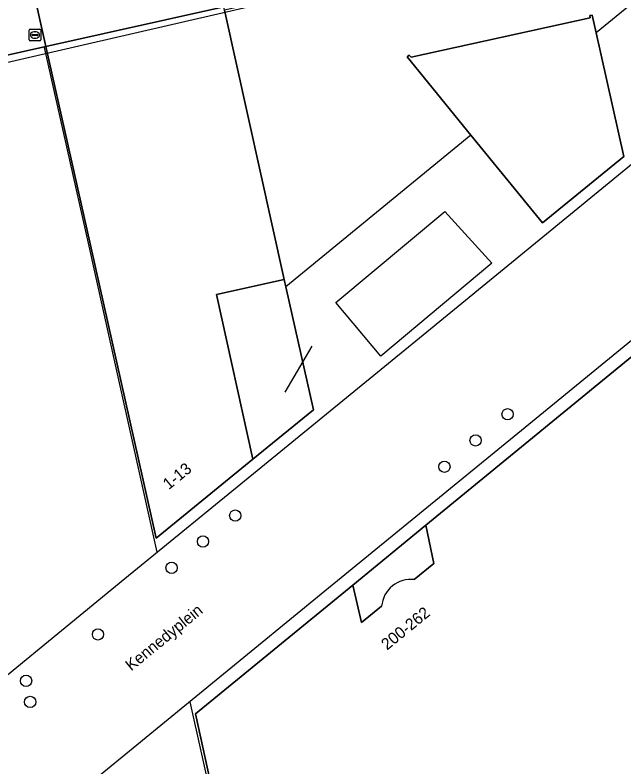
# Model space of a CAD drawing. Extents: x 160806 to 161707, y 383696 to 384148.
# Drawn here: x 161436.7 to 161489.3, y 383865.4 to 383930.4 of the extents above; entities that cross this region are included whole.
import ezdxf

# ---------------------------------------------------------------- set-up
doc = ezdxf.new("R2010")
doc.units = 0
for name, color, linetype in [('IMGEO_Boom', 7, 'Continuous'), ('IMGEO_Kolk', 7, 'Continuous'), ('IMGEO_Lage_trafo', 7, 'Continuous'), ('IMGEO_Lijnafwatering', 7, 'Continuous'), ('IMGEO_Muur', 7, 'Continuous'), ('IMGEO_Openbare_ruimte_label', 7, 'Continuous'), ('IMGEO_Pand', 7, 'Continuous'), ('IMGEO_Pand_nummerreeks', 7, 'Continuous'), ('IMGEO_Pand_overbouw', 7, 'Continuous'), ('IMGEO_Pand_vergunning_verleend', 7, 'Continuous'), ('IMGEO_Rijbaan_lokaal_open', 7, 'Continuous'), ('IMGEO_Voetgangersgebied_open', 7, 'Continuous'), ('IMGEO_Voetpad_open', 7, 'Continuous')]:
    doc.layers.add(name, color=color, linetype=linetype)

msp = doc.modelspace()

# ---------------------------------------------------------------- linework, layer by layer
at = {"layer": 'IMGEO_Boom'}
for centre in [(161479.28, 383895.862), (161476.511, 383893.603), (161473.815, 383891.327), (161455.746, 383887.101), (161452.959, 383884.86), (161450.245, 383882.583), (161443.887, 383876.827), (161437.673, 383872.817), (161438.028, 383870.992)]:
    msp.add_circle(centre, 0.489, dxfattribs=at)
at = {"layer": 'IMGEO_Kolk'}
for p, q in [((161437.942, 383928.219), (161437.942, 383929.071)), ((161438.017, 383929.145), (161438.869, 383929.145)), ((161438.43, 383928.925), (161438.455, 383928.925)), ((161438.943, 383929.071), (161438.943, 383928.219)), ((161438.869, 383928.145), (161438.017, 383928.145)), ((161438.201, 383928.639), (161438.201, 383928.651)), ((161438.639, 383928.602), (161438.241, 383928.602)), ((161438.244, 383928.688), (161438.642, 383928.688)), ((161438.453, 383928.365), (161438.428, 383928.365)), ((161438.685, 383928.651), (161438.685, 383928.639))]:
    msp.add_line(p, q, dxfattribs=at)
for points in [[(161437.942, 383928.219), (161437.942, 383929.071)], [(161438.017, 383929.145), (161438.869, 383929.145)], [(161438.943, 383929.071), (161438.943, 383928.219)], [(161438.869, 383928.145), (161438.017, 383928.145)]]:
    msp.add_lwpolyline(points, dxfattribs=at)
for centre, radius, start, end in [((161438.019, 383929.069), 0.0765, 91.55205, 178.44795), ((161438.019, 383929.069), 0.0765, 91.55205, 178.44795), ((161438.867, 383929.069), 0.0765, 1.55205, 88.44795), ((161438.867, 383929.069), 0.0765, 1.55205, 88.44795), ((161438.019, 383928.221), 0.0765, 181.55205, 268.44795), ((161438.019, 383928.221), 0.0765, 181.55205, 268.44795), ((161438.241, 383928.648), 0.0403, 85.87752, 175.75265), ((161438.238, 383928.638), 0.0366, 178.93798, 274.71019), ((161438.642, 383928.645), 0.043, 264.86636, 352.45326), ((161438.646, 383928.65), 0.0386, 1.73085, 96.63898), ((161438.867, 383928.221), 0.0765, 271.55205, 358.44795), ((161438.867, 383928.221), 0.0765, 271.55205, 358.44795)]:
    msp.add_arc(centre, radius, start, end, dxfattribs=at)
for centre, major_axis, ratio, start_param, end_param in [((161438.429, 383928.645), (-0.387, 0.002), 0.722429, 4.712389, 7.853982), ((161438.454, 383928.645), (-0.39, 0.002), 0.717154, 1.570796, 4.712389)]:
    msp.add_ellipse(centre, major_axis=major_axis, ratio=ratio, start_param=start_param, end_param=end_param, dxfattribs=at)
at = {"layer": 'IMGEO_Lage_trafo'}
msp.add_lwpolyline([(161476.093, 383919.982), (161482.285, 383912.417), (161489.323, 383918.15), (161486.939, 383928.817), (161486.593, 383930.363), (161486.368, 383930.313), (161486.412, 383930.118), (161470.932, 383926.734), (161470.783, 383926.909), (161470.586, 383926.74)], close=True, dxfattribs=at)
at = {"layer": 'IMGEO_Lijnafwatering'}
for points in [[(161502.28, 383941.387), (161486.939, 383928.817)], [(161443.569, 383908.415), (161443.126, 383910.384), (161439.258, 383927.569)], [(161498.731, 383924.609), (161485.032, 383913.398)], [(161476.093, 383919.982), (161460.12, 383906.88)], [(161485.032, 383913.398), (161471.334, 383902.187)], [(161448.986, 383883.942), (161443.569, 383908.415)], [(161497.266, 383908.212), (161480.466, 383894.464)], [(161471.334, 383902.187), (161457.635, 383890.976)], [(161460.045, 383897.758), (161462.396, 383901.756)], [(161480.466, 383894.464), (161463.161, 383880.303)], [(161457.635, 383890.976), (161446.22, 383881.633)], [(161446.22, 383881.633), (161430.238, 383868.553)], [(161463.161, 383880.303), (161446.281, 383866.489)], [(161451.826, 383870.993), (161453.9, 383861.703)], [(161446.281, 383866.489), (161429.508, 383852.763)]]:
    msp.add_lwpolyline(points, dxfattribs=at)
at = {"layer": 'IMGEO_Muur'}
msp.add_lwpolyline([(161433.038, 383926.234), (161439.383, 383927.651)], dxfattribs=at)
at = {"layer": 'IMGEO_Pand'}
msp.add_lwpolyline([(161454.121, 383906.21), (161459.978, 383907.51), (161454.819, 383930.799), (161454.756, 383931.084), (161439.383, 383927.651), (161443.236, 383910.469), (161448.9, 383885.137), (161457.261, 383891.97)], close=True, dxfattribs=at)
msp.add_lwpolyline([(161468.392, 383879.273), (161466.655, 383877.86), (161465.897, 383881.096), (161452.306, 383869.965), (161454.649, 383859.314), (161454.467, 383859.266), (161459.23, 383837.816), (161459.371, 383837.315), (161459.571, 383837.36), (161474.936, 383840.799), (161489.445, 383844.046), (161504.78, 383847.479), (161501.103, 383863.975), (161500.733, 383865.636), (161500.564, 383866.393), (161496.865, 383882.93), (161496.125, 383886.224), (161492.387, 383902.807), (161472.218, 383886.284), (161472.911, 383882.95), (161471.213, 383881.568)], dxfattribs=at)
msp.add_arc((161470.927, 383879.039), 2.546, 83.54263, 174.71692, dxfattribs=at)
at = {"layer": 'IMGEO_Pand_overbouw'}
for points in [[(161576.544, 383863.524), (161556.299, 383953.974), (161403.923, 383918.874), (161417.58, 383859.039), (161456.542, 383836.683)], [(161439.383, 383927.651), (161454.756, 383931.084), (161454.475, 383932.341), (161452.563, 383940.896), (161451.9, 383943.862), (161451.327, 383946.429), (161435.971, 383942.989), (161436.543, 383940.418), (161437.201, 383937.461), (161439.099, 383928.931)], [(161459.978, 383907.51), (161454.121, 383906.21), (161457.261, 383891.97), (161462.516, 383896.238), (161460.12, 383906.88)]]:
    msp.add_lwpolyline(points, close=True, dxfattribs=at)
for points in [[(161471.213, 383881.568), (161472.911, 383882.95), (161472.218, 383886.284), (161465.897, 383881.096)], [(161465.897, 383881.096), (161466.655, 383877.86), (161468.392, 383879.273)]]:
    msp.add_lwpolyline(points, dxfattribs=at)
msp.add_arc((161470.927, 383879.039), 2.546, 83.54263, 174.71692, dxfattribs=at)
at = {"layer": 'IMGEO_Pand_vergunning_verleend'}
msp.add_lwpolyline([(161464.441, 383905.505), (161473.848, 383913.38), (161477.926, 383908.926), (161468.313, 383900.88)], close=True, dxfattribs=at)
at = {"layer": 'IMGEO_Rijbaan_lokaal_open'}
msp.add_lwpolyline([(161445.071, 383940.79), (161436.914, 383938.751), (161437.201, 383937.461), (161439.383, 383927.651), (161454.756, 383931.084), (161452.563, 383940.896)], dxfattribs=at)
msp.add_lwpolyline([(161425.161, 383927.855), (161432.12, 383929.454), (161432.923, 383926.208), (161433.038, 383926.234), (161439.383, 383927.651), (161437.201, 383937.461), (161436.914, 383938.751), (161436.084, 383938.543), (161422.223, 383934.908), (161417.389, 383933.655), (161417.522, 383933.062), (161419.786, 383922.985), (161419.888, 383923.011), (161425.968, 383924.573)], close=True, dxfattribs=at)
at = {"layer": 'IMGEO_Voetgangersgebied_open'}
for points in [[(161502.28, 383941.387), (161484.102, 383937.319), (161484.378, 383936.019), (161477.167, 383934.318), (161476.856, 383935.709), (161454.819, 383930.799), (161459.978, 383907.51), (161460.12, 383906.88), (161462.516, 383896.238), (161457.261, 383891.97), (161448.9, 383885.137), (161443.236, 383910.469), (161439.383, 383927.651), (161433.038, 383926.234), (161433.18, 383925.675), (161424.076, 383923.368), (161420.469, 383920.416), (161420.775, 383919.046), (161424.946, 383922.401), (161429.992, 383900.129), (161430.119, 383899.986), (161430.247, 383899.844)], [(161454.649, 383859.314), (161452.306, 383869.965), (161465.897, 383881.096), (161472.218, 383886.284), (161492.387, 383902.807), (161497.417, 383906.928), (161499.226, 383908.41), (161507.57, 383871.236), (161502.965, 383867.464), (161522.234, 383871.748), (161518.425, 383888.826), (161511.932, 383917.834)]]:
    msp.add_lwpolyline(points, dxfattribs=at)
msp.add_lwpolyline([(161482.285, 383912.417), (161476.093, 383919.982), (161470.586, 383926.74), (161470.783, 383926.909), (161470.932, 383926.734), (161486.412, 383930.118), (161486.368, 383930.313), (161486.593, 383930.363), (161486.939, 383928.817), (161489.323, 383918.15)], close=True, dxfattribs=at)
at = {"layer": 'IMGEO_Voetpad_open'}
msp.add_lwpolyline([(161457.261, 383891.97), (161462.516, 383896.238), (161460.12, 383906.88), (161459.978, 383907.51), (161454.121, 383906.21)], close=True, dxfattribs=at)
msp.add_lwpolyline([(161471.213, 383881.568), (161472.911, 383882.95), (161472.218, 383886.284), (161465.897, 383881.096), (161466.655, 383877.86), (161468.392, 383879.273)], dxfattribs=at)
msp.add_arc((161470.927, 383879.039), 2.546, 83.54263, 174.71692, dxfattribs=at)

# ---------------------------------------------------------------- texts
at = {"layer": 'IMGEO_Openbare_ruimte_label'}
msp.add_text('Kennedyplein', height=1, rotation=39.19669, dxfattribs=at).set_placement((161446.756, 383873.621))
at = {"layer": 'IMGEO_Pand_nummerreeks'}
for s, rotation, p in [('1-13', 39.25778, (161449.999, 383889.289)), ('200-262', 39.13253, (161468.862, 383875.427))]:
    msp.add_text(s, height=1, rotation=rotation, dxfattribs=at).set_placement(p)

doc.saveas('drawing.dxf')
